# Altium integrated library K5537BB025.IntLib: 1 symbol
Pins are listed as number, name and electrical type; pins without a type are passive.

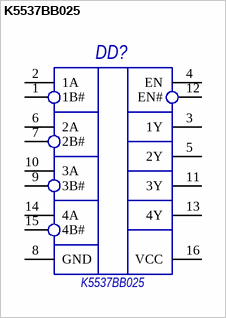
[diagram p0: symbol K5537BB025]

## K5537BB025
designator DD?
footprint 5130.16-AH3
pins: 1 1B#, 2 1A, 3 1Y, 4 EN, 5 2Y, 6 2A, 7 2B#, 8 GND, 9 3B#, 10 3A, 11 3Y, 12 EN#, 13 4Y, 14 4A, 15 4B#, 16 VCC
